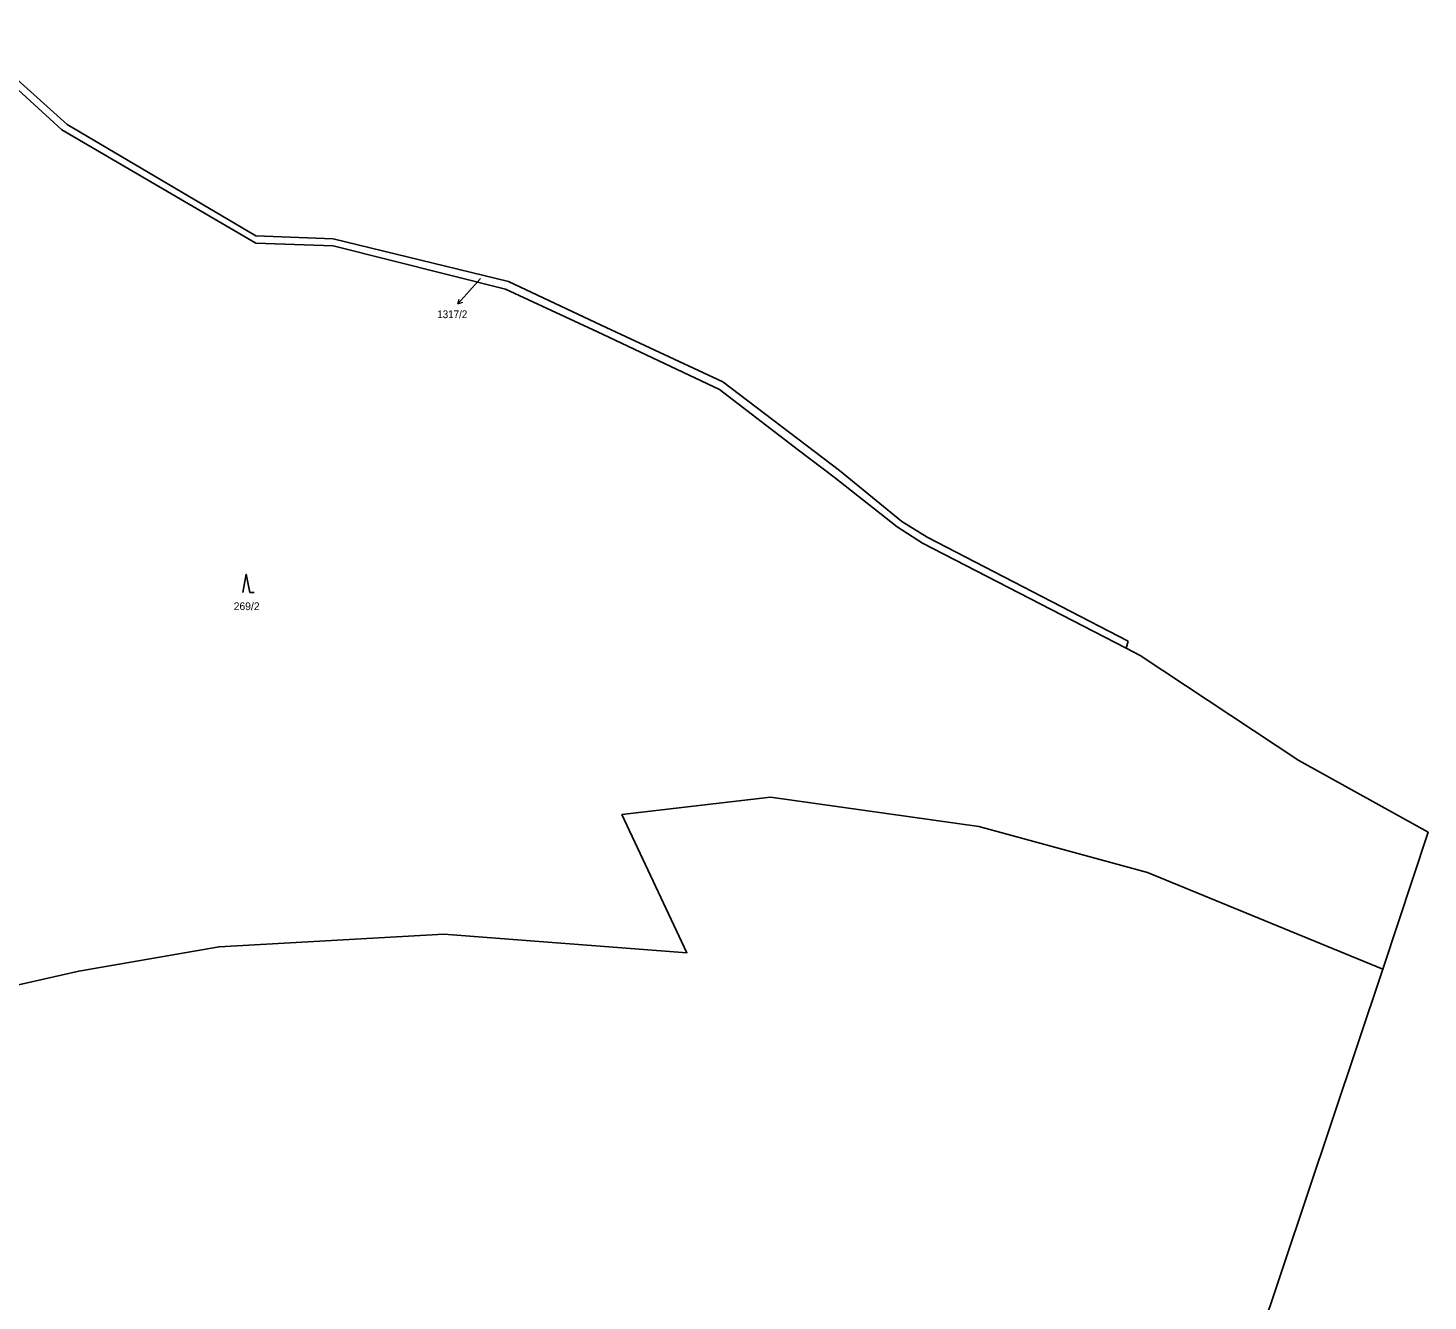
# Model space of a CAD drawing. Extents: x -872229 to -869198, y -1075981 to -1074329.
# Drawn here: x -869694.9 to -869387.3, y -1074938.2 to -1074658.6 of the extents above; entities that cross this region are included whole.
import ezdxf
from ezdxf.enums import TextEntityAlignment as Align

# ---------------------------------------------------------------- set-up
doc = ezdxf.new("R2010")
doc.units = 0
doc.header["$LTSCALE"] = 0.68
for name, color, linetype, lineweight in [('1', 7, 'Continuous', 25), ('3', 7, 'Continuous', 25), ('7', 7, 'Continuous', 13)]:
    doc.layers.add(name, color=color, linetype=linetype, lineweight=lineweight)
doc.layers.add('2', color=7, linetype='Continuous')

msp = doc.modelspace()

# ---------------------------------------------------------------- linework, layer by layer
at = {"layer": '1'}
msp.add_line((-869453.23, -1074793.29), (-869453.66, -1074794.85), dxfattribs=at)
for points in [[(-869453.23, -1074793.29), (-869497.35, -1074770.43), (-869502.91, -1074766.99), (-869516.66, -1074755.78), (-869542.23, -1074736.35), (-869569.01, -1074723.84), (-869589.32, -1074714.31), (-869627.88, -1074704.89), (-869644.84, -1074704.23), (-869686.29, -1074679.82), (-869709.86, -1074658.59), (-869711.15, -1074659.32)], [(-869453.66, -1074794.85), (-869498.36, -1074771.77), (-869503.98, -1074768.2), (-869517.76, -1074757.22), (-869525.6, -1074751.31), (-869543.02, -1074738.02), (-869569.82, -1074725.31), (-869590.03, -1074715.95), (-869627.87, -1074706.45), (-869644.88, -1074705.89), (-869687.49, -1074680.97), (-869701.44, -1074668.21)], [(-869453.66, -1074794.85), (-869450.55, -1074796.46), (-869415.69, -1074819.52)], [(-869415.69, -1074819.52), (-869387.33, -1074835.26), (-869397.27, -1074865.36), (-869463.59, -1075063.5)], [(-869397.27, -1074865.36), (-869448.98, -1074844.13), (-869486.01, -1074834.03), (-869531.78, -1074827.54), (-869564.41, -1074831.36), (-869550.14, -1074861.73), (-869603.53, -1074857.64), (-869652.94, -1074860.42), (-869683.77, -1074865.74), (-869722.65, -1074874.59), (-869772.21, -1074877.32), (-869775.77, -1074861.05), (-869776.86, -1074851.73)]]:
    msp.add_lwpolyline(points, dxfattribs=at)
at = {"layer": '3'}
msp.add_line((-869646.21, -1074782.6), (-869645.214, -1074782.6), dxfattribs=at)
msp.add_lwpolyline([(-869646.21, -1074782.6), (-869646.96, -1074778.6), (-869647.71, -1074782.6)], dxfattribs=at)
at = {"layer": '7'}
msp.add_line((-869600.449, -1074719.215), (-869599.414, -1074718.788), dxfattribs=at)
msp.add_lwpolyline([(-869595.53, -1074713.6), (-869598.48, -1074716.95), (-869600.449, -1074719.215), (-869600.17, -1074718.131)], dxfattribs=at)

# ---------------------------------------------------------------- texts
at = {"layer": '2', "width": 0.95}
msp.add_text('1317/2', height=1.7, dxfattribs=at).set_placement((-869601.699, -1074722.32), align=Align.CENTER)
at = {"layer": '2'}
msp.add_text('269/2', height=1.7, dxfattribs=at).set_placement((-869649.72, -1074786.46))

doc.saveas('drawing.dxf')
